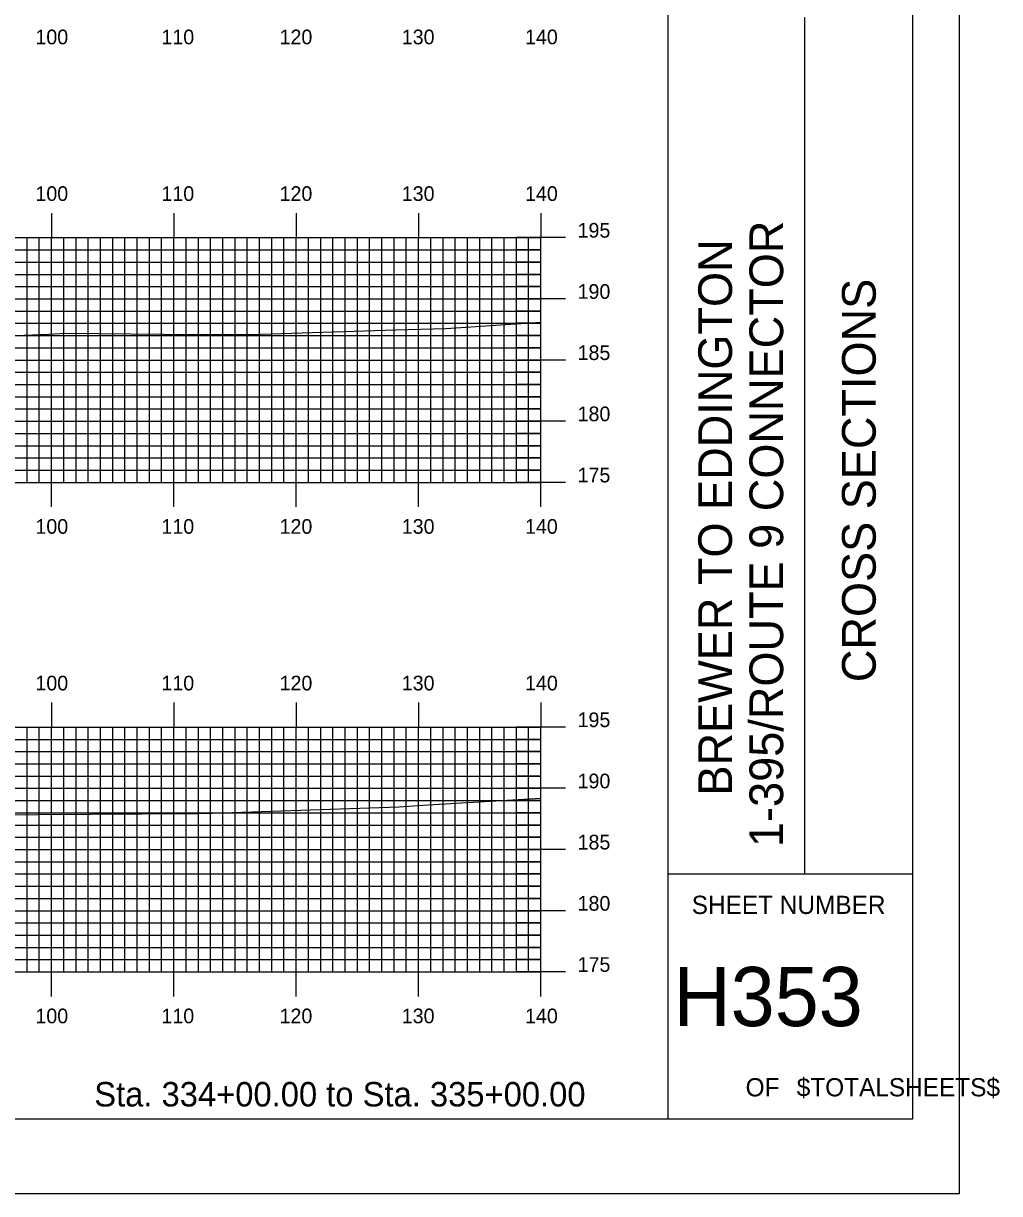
# Model space of a CAD drawing. Extents: x 1823179 to 1823522, y 442591 to 442811.
# Drawn here: x 1823442.5 to 1823522.3, y 442590.5 to 442686.2 of the extents above; entities that cross this region are included whole.
import ezdxf

# ---------------------------------------------------------------- set-up
doc = ezdxf.new("R2010")
doc.units = 0
for name, color, linetype in [('BORDER', 7, 'Continuous'), ('H_V ANNOTATION', 7, 'Continuous'), ('MAJOR', 7, 'Continuous'), ('MINOR', 7, 'Continuous'), ('PLOT BOUNDARY', 7, 'Continuous'), ('S_Roadway_Centerline', 7, 'Continuous')]:
    doc.layers.add(name, color=color, linetype=linetype)

msp = doc.modelspace()

# ---------------------------------------------------------------- linework, layer by layer
at = {"layer": 'BORDER'}
for p, q in [((1823495.196, 442596.665), (1823495.196, 442806.665)), ((1823506.378, 442616.671), (1823506.378, 442686.671)), ((1823495.196, 442616.671), (1823515.196, 442616.671))]:
    msp.add_line(p, q, dxfattribs=at)
msp.add_lwpolyline([(1823195.196, 442596.665), (1823515.196, 442596.665), (1823515.196, 442806.665), (1823195.196, 442806.665)], close=True, dxfattribs=at)
at = {"layer": 'MAJOR'}
for p, q in [((1823444.796, 442670.669), (1823444.796, 442668.665)), ((1823454.796, 442670.669), (1823454.796, 442668.665)), ((1823464.796, 442670.669), (1823464.796, 442668.665)), ((1823474.796, 442670.669), (1823474.796, 442668.665)), ((1823484.796, 442670.669), (1823484.796, 442668.665)), ((1823204.796, 442668.665), (1823484.796, 442668.665)), ((1823204.796, 442668.665), (1823484.796, 442668.665)), ((1823444.796, 442648.665), (1823444.796, 442668.665)), ((1823454.796, 442648.665), (1823454.796, 442668.665)), ((1823464.796, 442648.665), (1823464.796, 442668.665)), ((1823474.796, 442648.665), (1823474.796, 442668.665)), ((1823486.8, 442668.665), (1823482.792, 442668.665)), ((1823484.796, 442648.665), (1823484.796, 442668.665)), ((1823484.796, 442648.665), (1823484.796, 442668.665)), ((1823204.796, 442663.665), (1823484.796, 442663.665)), ((1823486.8, 442663.665), (1823482.792, 442663.665)), ((1823204.796, 442658.665), (1823484.796, 442658.665)), ((1823486.8, 442658.665), (1823482.792, 442658.665)), ((1823204.796, 442653.665), (1823484.796, 442653.665)), ((1823486.8, 442653.665), (1823482.792, 442653.665)), ((1823204.796, 442648.665), (1823484.796, 442648.665)), ((1823204.796, 442648.665), (1823484.796, 442648.665)), ((1823444.796, 442646.661), (1823444.796, 442648.665)), ((1823454.796, 442646.661), (1823454.796, 442648.665)), ((1823464.796, 442646.661), (1823464.796, 442648.665)), ((1823474.796, 442646.661), (1823474.796, 442648.665)), ((1823486.8, 442648.665), (1823482.792, 442648.665)), ((1823484.796, 442646.661), (1823484.796, 442648.665)), ((1823444.796, 442630.669), (1823444.796, 442628.665)), ((1823454.796, 442630.669), (1823454.796, 442628.665)), ((1823464.796, 442630.669), (1823464.796, 442628.665)), ((1823474.796, 442630.669), (1823474.796, 442628.665)), ((1823484.796, 442630.669), (1823484.796, 442628.665)), ((1823204.796, 442628.665), (1823484.796, 442628.665)), ((1823204.796, 442628.665), (1823484.796, 442628.665)), ((1823444.796, 442608.665), (1823444.796, 442628.665)), ((1823454.796, 442608.665), (1823454.796, 442628.665)), ((1823464.796, 442608.665), (1823464.796, 442628.665)), ((1823474.796, 442608.665), (1823474.796, 442628.665)), ((1823486.8, 442628.665), (1823482.792, 442628.665)), ((1823484.796, 442608.665), (1823484.796, 442628.665)), ((1823484.796, 442608.665), (1823484.796, 442628.665)), ((1823204.796, 442623.665), (1823484.796, 442623.665)), ((1823486.8, 442623.665), (1823482.792, 442623.665)), ((1823204.796, 442618.665), (1823484.796, 442618.665)), ((1823486.8, 442618.665), (1823482.792, 442618.665)), ((1823204.796, 442613.665), (1823484.796, 442613.665)), ((1823486.8, 442613.665), (1823482.792, 442613.665)), ((1823204.796, 442608.665), (1823484.796, 442608.665)), ((1823204.796, 442608.665), (1823484.796, 442608.665)), ((1823444.796, 442606.661), (1823444.796, 442608.665)), ((1823454.796, 442606.661), (1823454.796, 442608.665)), ((1823464.796, 442606.661), (1823464.796, 442608.665)), ((1823474.796, 442606.661), (1823474.796, 442608.665)), ((1823486.8, 442608.665), (1823482.792, 442608.665)), ((1823484.796, 442606.661), (1823484.796, 442608.665))]:
    msp.add_line(p, q, dxfattribs=at)
at = {"layer": 'MINOR'}
for p, q in [((1823442.796, 442648.665), (1823442.796, 442668.665)), ((1823443.796, 442648.665), (1823443.796, 442668.665)), ((1823445.796, 442648.665), (1823445.796, 442668.665)), ((1823446.796, 442648.665), (1823446.796, 442668.665)), ((1823447.796, 442648.665), (1823447.796, 442668.665)), ((1823448.796, 442648.665), (1823448.796, 442668.665)), ((1823449.796, 442648.665), (1823449.796, 442668.665)), ((1823450.796, 442648.665), (1823450.796, 442668.665)), ((1823451.796, 442648.665), (1823451.796, 442668.665)), ((1823452.796, 442648.665), (1823452.796, 442668.665)), ((1823453.796, 442648.665), (1823453.796, 442668.665)), ((1823455.796, 442648.665), (1823455.796, 442668.665)), ((1823456.796, 442648.665), (1823456.796, 442668.665)), ((1823457.796, 442648.665), (1823457.796, 442668.665)), ((1823458.796, 442648.665), (1823458.796, 442668.665)), ((1823459.796, 442648.665), (1823459.796, 442668.665)), ((1823460.796, 442648.665), (1823460.796, 442668.665)), ((1823461.796, 442648.665), (1823461.796, 442668.665)), ((1823462.796, 442648.665), (1823462.796, 442668.665)), ((1823463.796, 442648.665), (1823463.796, 442668.665)), ((1823465.796, 442648.665), (1823465.796, 442668.665)), ((1823466.796, 442648.665), (1823466.796, 442668.665)), ((1823467.796, 442648.665), (1823467.796, 442668.665)), ((1823468.796, 442648.665), (1823468.796, 442668.665)), ((1823469.796, 442648.665), (1823469.796, 442668.665)), ((1823470.796, 442648.665), (1823470.796, 442668.665)), ((1823471.796, 442648.665), (1823471.796, 442668.665)), ((1823472.796, 442648.665), (1823472.796, 442668.665)), ((1823473.796, 442648.665), (1823473.796, 442668.665)), ((1823475.796, 442648.665), (1823475.796, 442668.665)), ((1823476.796, 442648.665), (1823476.796, 442668.665)), ((1823477.796, 442648.665), (1823477.796, 442668.665)), ((1823478.796, 442648.665), (1823478.796, 442668.665)), ((1823479.796, 442648.665), (1823479.796, 442668.665)), ((1823480.796, 442648.665), (1823480.796, 442668.665)), ((1823481.796, 442648.665), (1823481.796, 442668.665)), ((1823482.796, 442648.665), (1823482.796, 442668.665)), ((1823483.796, 442648.665), (1823483.796, 442668.665)), ((1823204.796, 442667.665), (1823484.796, 442667.665)), ((1823484.796, 442667.665), (1823482.792, 442667.665)), ((1823204.796, 442666.665), (1823484.796, 442666.665)), ((1823484.796, 442666.665), (1823482.792, 442666.665)), ((1823204.796, 442665.665), (1823484.796, 442665.665)), ((1823484.796, 442665.665), (1823482.792, 442665.665)), ((1823204.796, 442664.665), (1823484.796, 442664.665)), ((1823484.796, 442664.665), (1823482.792, 442664.665)), ((1823204.796, 442662.665), (1823484.796, 442662.665)), ((1823484.796, 442662.665), (1823482.792, 442662.665)), ((1823204.796, 442661.665), (1823484.796, 442661.665)), ((1823484.796, 442661.665), (1823482.792, 442661.665)), ((1823204.796, 442660.665), (1823484.796, 442660.665)), ((1823484.796, 442660.665), (1823482.792, 442660.665)), ((1823204.796, 442659.665), (1823484.796, 442659.665)), ((1823484.796, 442659.665), (1823482.792, 442659.665)), ((1823204.796, 442657.665), (1823484.796, 442657.665)), ((1823484.796, 442657.665), (1823482.792, 442657.665)), ((1823204.796, 442656.665), (1823484.796, 442656.665)), ((1823484.796, 442656.665), (1823482.792, 442656.665)), ((1823204.796, 442655.665), (1823484.796, 442655.665)), ((1823484.796, 442655.665), (1823482.792, 442655.665)), ((1823204.796, 442654.665), (1823484.796, 442654.665)), ((1823484.796, 442654.665), (1823482.792, 442654.665)), ((1823204.796, 442652.665), (1823484.796, 442652.665)), ((1823484.796, 442652.665), (1823482.792, 442652.665)), ((1823204.796, 442651.665), (1823484.796, 442651.665)), ((1823484.796, 442651.665), (1823482.792, 442651.665)), ((1823204.796, 442650.665), (1823484.796, 442650.665)), ((1823484.796, 442650.665), (1823482.792, 442650.665)), ((1823204.796, 442649.665), (1823484.796, 442649.665)), ((1823484.796, 442649.665), (1823482.792, 442649.665)), ((1823442.796, 442608.665), (1823442.796, 442628.665)), ((1823443.796, 442608.665), (1823443.796, 442628.665)), ((1823445.796, 442608.665), (1823445.796, 442628.665)), ((1823446.796, 442608.665), (1823446.796, 442628.665)), ((1823447.796, 442608.665), (1823447.796, 442628.665)), ((1823448.796, 442608.665), (1823448.796, 442628.665)), ((1823449.796, 442608.665), (1823449.796, 442628.665)), ((1823450.796, 442608.665), (1823450.796, 442628.665)), ((1823451.796, 442608.665), (1823451.796, 442628.665)), ((1823452.796, 442608.665), (1823452.796, 442628.665)), ((1823453.796, 442608.665), (1823453.796, 442628.665)), ((1823455.796, 442608.665), (1823455.796, 442628.665)), ((1823456.796, 442608.665), (1823456.796, 442628.665)), ((1823457.796, 442608.665), (1823457.796, 442628.665)), ((1823458.796, 442608.665), (1823458.796, 442628.665)), ((1823459.796, 442608.665), (1823459.796, 442628.665)), ((1823460.796, 442608.665), (1823460.796, 442628.665)), ((1823461.796, 442608.665), (1823461.796, 442628.665)), ((1823462.796, 442608.665), (1823462.796, 442628.665)), ((1823463.796, 442608.665), (1823463.796, 442628.665)), ((1823465.796, 442608.665), (1823465.796, 442628.665)), ((1823466.796, 442608.665), (1823466.796, 442628.665)), ((1823467.796, 442608.665), (1823467.796, 442628.665)), ((1823468.796, 442608.665), (1823468.796, 442628.665)), ((1823469.796, 442608.665), (1823469.796, 442628.665)), ((1823470.796, 442608.665), (1823470.796, 442628.665)), ((1823471.796, 442608.665), (1823471.796, 442628.665)), ((1823472.796, 442608.665), (1823472.796, 442628.665)), ((1823473.796, 442608.665), (1823473.796, 442628.665)), ((1823475.796, 442608.665), (1823475.796, 442628.665)), ((1823476.796, 442608.665), (1823476.796, 442628.665)), ((1823477.796, 442608.665), (1823477.796, 442628.665)), ((1823478.796, 442608.665), (1823478.796, 442628.665)), ((1823479.796, 442608.665), (1823479.796, 442628.665)), ((1823480.796, 442608.665), (1823480.796, 442628.665)), ((1823481.796, 442608.665), (1823481.796, 442628.665)), ((1823482.796, 442608.665), (1823482.796, 442628.665)), ((1823483.796, 442608.665), (1823483.796, 442628.665)), ((1823204.796, 442627.665), (1823484.796, 442627.665)), ((1823484.796, 442627.665), (1823482.792, 442627.665)), ((1823204.796, 442626.665), (1823484.796, 442626.665)), ((1823484.796, 442626.665), (1823482.792, 442626.665)), ((1823204.796, 442625.665), (1823484.796, 442625.665)), ((1823484.796, 442625.665), (1823482.792, 442625.665)), ((1823204.796, 442624.665), (1823484.796, 442624.665)), ((1823484.796, 442624.665), (1823482.792, 442624.665)), ((1823204.796, 442622.665), (1823484.796, 442622.665)), ((1823484.796, 442622.665), (1823482.792, 442622.665)), ((1823204.796, 442621.665), (1823484.796, 442621.665)), ((1823484.796, 442621.665), (1823482.792, 442621.665)), ((1823204.796, 442620.665), (1823484.796, 442620.665)), ((1823484.796, 442620.665), (1823482.792, 442620.665)), ((1823204.796, 442619.665), (1823484.796, 442619.665)), ((1823484.796, 442619.665), (1823482.792, 442619.665)), ((1823204.796, 442617.665), (1823484.796, 442617.665)), ((1823484.796, 442617.665), (1823482.792, 442617.665)), ((1823204.796, 442616.665), (1823484.796, 442616.665)), ((1823484.796, 442616.665), (1823482.792, 442616.665)), ((1823204.796, 442615.665), (1823484.796, 442615.665)), ((1823484.796, 442615.665), (1823482.792, 442615.665)), ((1823204.796, 442614.665), (1823484.796, 442614.665)), ((1823484.796, 442614.665), (1823482.792, 442614.665)), ((1823204.796, 442612.665), (1823484.796, 442612.665)), ((1823484.796, 442612.665), (1823482.792, 442612.665)), ((1823204.796, 442611.665), (1823484.796, 442611.665)), ((1823484.796, 442611.665), (1823482.792, 442611.665)), ((1823204.796, 442610.665), (1823484.796, 442610.665)), ((1823484.796, 442610.665), (1823482.792, 442610.665)), ((1823204.796, 442609.665), (1823484.796, 442609.665)), ((1823484.796, 442609.665), (1823482.792, 442609.665))]:
    msp.add_line(p, q, dxfattribs=at)
at = {"layer": 'PLOT BOUNDARY'}
msp.add_lwpolyline([(1823179.009, 442590.547), (1823519.009, 442590.547), (1823519.009, 442810.547), (1823179.009, 442810.547)], close=True, dxfattribs=at)
at = {"layer": 'S_Roadway_Centerline'}
for points in [[(1823441.916, 442660.681), (1823444.54, 442660.788), (1823445.972, 442660.864), (1823453.936, 442660.782), (1823461.053, 442660.759), (1823472.921, 442661.125), (1823477.038, 442661.247), (1823484.796, 442661.763)], [(1823439.896, 442621.481), (1823443.682, 442621.53), (1823456.493, 442621.595), (1823456.77, 442621.607), (1823457.934, 442621.64), (1823473.202, 442622.163), (1823475.571, 442622.312), (1823484.796, 442622.857)]]:
    msp.add_lwpolyline(points, dxfattribs=at)

# ---------------------------------------------------------------- texts
at = {"layer": 'BORDER'}
for s, p in [('1-395/ROUTE 9 CONNECTOR', (1823504.599, 442618.865)), ('BREWER TO EDDINGTON', (1823500.42, 442623.074)), ('CROSS SECTIONS', (1823512.165, 442632.339))]:
    msp.add_text(s, height=2.75575, rotation=90, dxfattribs=at).set_placement(p)
for s, height, p in [('SHEET NUMBER', 1.49054, (1823497.126, 442613.398)), ('H353', 4.8388, (1823495.635, 442604.23)), ('OF', 1.4905, (1823501.529, 442598.491)), ('$TOTALSHEETS$', 1.49054, (1823505.709, 442598.491))]:
    msp.add_text(s, height=height, dxfattribs=at).set_placement(p)
at = {"layer": 'H_V ANNOTATION'}
for s, height, p in [('100', 1.2, (1823443.479, 442684.465)), ('110', 1.2, (1823453.779, 442684.465)), ('120', 1.2, (1823463.436, 442684.465)), ('130', 1.2, (1823473.425, 442684.465)), ('140', 1.2, (1823483.5, 442684.465)), ('100', 1.2, (1823443.479, 442671.665)), ('110', 1.2, (1823453.779, 442671.665)), ('120', 1.2, (1823463.436, 442671.665)), ('130', 1.2, (1823473.425, 442671.665)), ('140', 1.2, (1823483.5, 442671.665)), ('195', 1.2, (1823487.796, 442668.665)), ('190', 1.2, (1823487.796, 442663.665)), ('185', 1.2, (1823487.796, 442658.665)), ('180', 1.2, (1823487.796, 442653.665)), ('175', 1.2, (1823487.796, 442648.665)), ('100', 1.2, (1823443.479, 442644.465)), ('110', 1.2, (1823453.779, 442644.465)), ('120', 1.2, (1823463.436, 442644.465)), ('130', 1.2, (1823473.425, 442644.465)), ('140', 1.2, (1823483.5, 442644.465)), ('100', 1.2, (1823443.479, 442631.665)), ('110', 1.2, (1823453.779, 442631.665)), ('120', 1.2, (1823463.436, 442631.665)), ('130', 1.2, (1823473.425, 442631.665)), ('140', 1.2, (1823483.5, 442631.665)), ('195', 1.2, (1823487.796, 442628.665)), ('190', 1.2, (1823487.796, 442623.665)), ('185', 1.2, (1823487.796, 442618.665)), ('180', 1.2, (1823487.796, 442613.665)), ('175', 1.2, (1823487.796, 442608.665)), ('100', 1.2, (1823443.479, 442604.465)), ('110', 1.2, (1823453.779, 442604.465)), ('120', 1.2, (1823463.436, 442604.465)), ('130', 1.2, (1823473.425, 442604.465)), ('140', 1.2, (1823483.5, 442604.465)), ('Sta. 334+00.00 to Sta. 335+00.00', 2.0004, (1823448.287, 442597.665))]:
    msp.add_text(s, height=height, dxfattribs=at).set_placement(p)

doc.saveas('drawing.dxf')
